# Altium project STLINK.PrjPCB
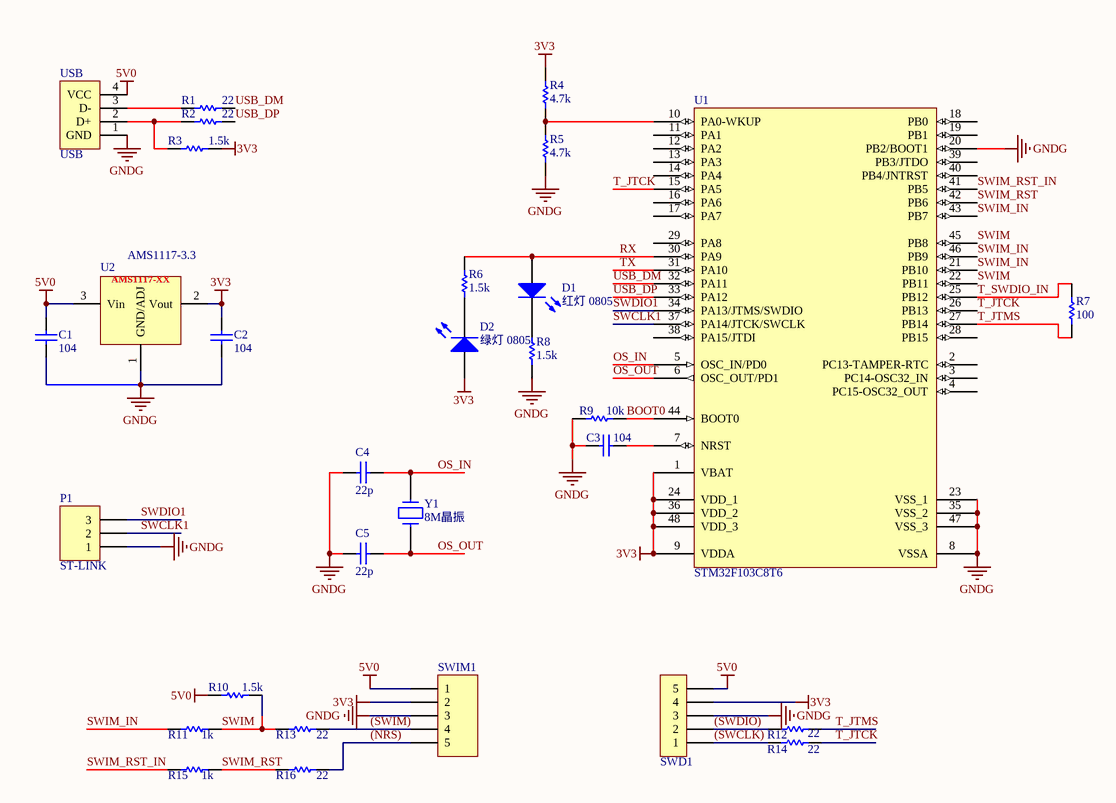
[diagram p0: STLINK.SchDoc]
1 sheet, 30 parts. Net scope: global (net labels, ports and power ports of the same name join across sheets).
Board file: STLINK.PcbDoc

## Sheet STLINK.SchDoc
size A4

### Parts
C1  104  [0603_C]
C2  104  [0603_C]
C3  104  [0603_C]
C4  value 22p  [0603_C]  (hidden comment: 22pf)
C5  value 22p  [0603_C]  (hidden comment: 22pf)
D1  红灯 0805  [LC-0805_LED_S1]
D2  绿灯 0805  [LC-0805_LED_S1]
P1  ST-LINK  [HDR1X3]
R1  value 22  [0603_R]  (hidden comment: 22R)
R2  value 22  [0603_R]  (hidden comment: 22R)
R3  1.5k  [0603_R]
R4  4.7k  [0603_R]
R5  4.7k  [0603_R]
R6  1.5k  [0603_R]
R7  value 100  [0603_R]  (hidden comment: 100R)
R8  1.5k  [0603_R]
R9  10k  [0603_R]
R10  1.5k  [0603_R]
R11  1k  [0603_R]
R12  value 22  [0603_R]  (hidden comment: 22R)
R13  value 22  [0603_R]  (hidden comment: 22R)
R14  value 22  [0603_R]  (hidden comment: 22R)
R15  1k  [0603_R]
R16  value 22  [0603_R]  (hidden comment: 22R)
SWD1  Head5  [HEADER 5]  (value not drawn)
SWIM1  Header 5  [HEADER 5]  (value not drawn)
U1  STM32F103C8T6  [LQFP48_N]
U2  AMS1117-3.3  [SOT-223]
USB  USB  [USB_A_G]
Y1  8M晶振  [XTAL_2]

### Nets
3V3: C2.2 D2.A R3.2 R4.2 SWD1.4 SWIM1.2 U1.1(VBAT) U1.9(VDDA) U1.24(VDD_1) U1.36(VDD_2) U1.48(VDD_3) U2.2(Vout)
5V0: C1.2 R10.1 SWD1.5 SWIM1.1 U2.3(Vin) USB.4(VCC)
GNDG: C1.1 C2.1 C3.1 C4.1 C5.1 P1.1 R5.1 R8.1 R9.1 SWD1.3 SWIM1.3 U1.8(VSSA) U1.20(PB2/BOOT1) U1.23(VSS_1) U1.35(VSS_2) U1.47(VSS_3) U2.1(GND/ADJ) USB.1(GND)
(NRS): R16.1 SWIM1.5
(SWCLK): R14.1 SWD1.1
(SWDIO): R12.1 SWD1.2
(SWIM): R13.1 SWIM1.4
BOOT0: R9.2 U1.44(BOOT0)
OS_IN: C4.2 U1.5(OSC_IN/PD0) Y1.2
OS_OUT: C5.2 U1.6(OSC_OUT/PD1) Y1.1
RX: D1.A R6.2 U1.30(PA9)
SWCLK1: P1.2 U1.37(PA14/JTCK/SWCLK)
SWDIO1: P1.3 U1.34(PA13/JTMS/SWDIO)
SWIM: R10.2 R11.2 R13.2 U1.22(PB11) U1.45(PB8)
SWIM_IN: R11.1 U1.21(PB10) U1.43(PB7) U1.46(PB9)
SWIM_RST: R15.2 R16.2 U1.42(PB6)
SWIM_RST_IN: R15.1 U1.41(PB5)
T_JTCK: R14.2 U1.15(PA5) U1.26(PB13)
T_JTMS: R7.1 R12.2 U1.27(PB14)
T_SWDIO_IN: R7.2 U1.25(PB12)
TX: U1.31(PA10)
USB_DM: R1.2 U1.32(PA11)
USB_DP: R2.2 U1.33(PA12)
NetC3_2: C3.2 U1.7(NRST)
NetD1_K: D1.K R8.2
NetD2_K: D2.K R6.1
NetR1_1: R1.1 USB.3(D-)
NetR2_1: R2.1 R3.1 USB.2(D+)
NetR4_1: R4.1 R5.2 U1.10(PA0-WKUP)

Not connected (* = marked no-connect by the designer): U1 2(PC13-TAMPER-RTC) 3(PC14-OSC32_IN) 4(PC15-OSC32_OUT) 11(PA1) 12(PA2) 13(PA3) 14(PA4) 16(PA6) 17(PA7) 18(PB0) 19(PB1) 28(PB15) 29(PA8) 38(PA15/JTDI) 39(PB3/JTDO) 40(PB4/JNTRST)

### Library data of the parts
C1-C5 = Cap
D1 D2 = 0805 蓝灯: 发光二极管
P1 = Header 3: Header, 3-Pin
R1-R16 = RES
SWD1 = HEAD 5
SWIM1 = Header 5: Header, 5-Pin
U1 = STM32F103C8T6: STM32 ARM-based 32-bit MCU with 64 Kbytes Flash, 48-pin LQFP, Industrial Temperature
U2 = AMS1117-XX: AMS   800mA LOW DROPOUT VOLTAGE REGULATOR
USB = USB_G
Y1 = XTAL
